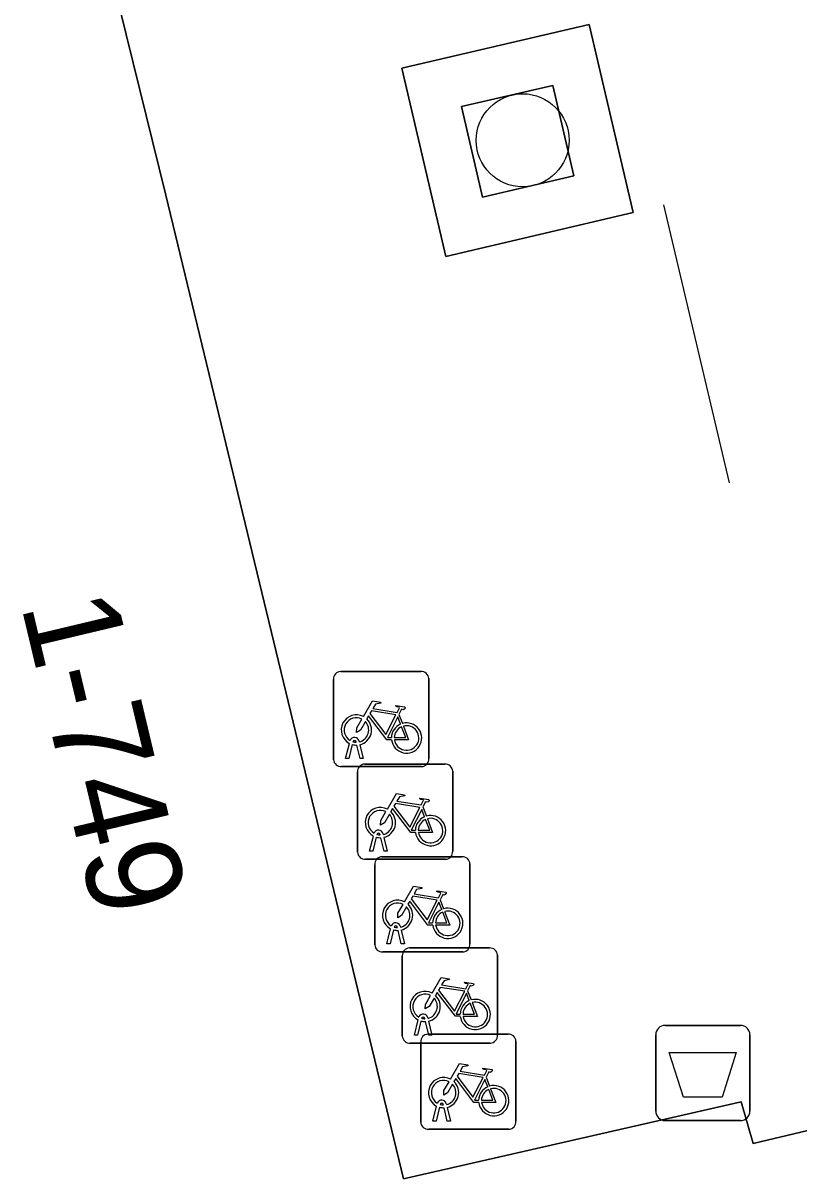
# Model space of a CAD drawing. Extents: x 160675 to 161153, y 383241 to 383714.
# Drawn here: x 160917.27 to 160925.43, y 383491.7 to 383503.84 of the extents above; entities that cross this region are included whole.
import ezdxf

# ---------------------------------------------------------------- set-up
doc = ezdxf.new("R2010")
doc.units = 0
for name, color, linetype in [('IMGEO_Afvalbak', 7, 'Continuous'), ('IMGEO_Boom', 7, 'Continuous'), ('IMGEO_Fietsenrek', 7, 'Continuous'), ('IMGEO_Groenvoorziening', 7, 'Continuous'), ('IMGEO_Lijnafwatering', 7, 'Continuous'), ('IMGEO_Muur', 7, 'Continuous'), ('IMGEO_Pand', 7, 'Continuous'), ('IMGEO_Pand_nummerreeks', 7, 'Continuous'), ('IMGEO_Voetpad_open', 7, 'Continuous')]:
    doc.layers.add(name, color=color, linetype=linetype)

msp = doc.modelspace()

# ---------------------------------------------------------------- linework, layer by layer
at = {"layer": 'IMGEO_Afvalbak'}
for p, q in [((160924.022, 383493.31), (160924.812, 383493.31)), ((160924.812, 383493.31), (160924.022, 383493.31)), ((160923.922, 383492.41), (160923.922, 383493.21)), ((160923.922, 383493.21), (160923.922, 383492.41)), ((160924.912, 383493.21), (160924.912, 383492.41)), ((160924.912, 383492.41), (160924.912, 383493.21)), ((160924.812, 383492.31), (160924.022, 383492.31)), ((160924.022, 383492.31), (160924.812, 383492.31))]:
    msp.add_line(p, q, dxfattribs=at)
msp.add_lwpolyline([(160924.065, 383493.024), (160924.769, 383493.024), (160924.62, 383492.554), (160924.214, 383492.554), (160924.065, 383493.024)], dxfattribs=at)
for centre, start, end in [((160924.022, 383493.21), 90, 180), ((160924.022, 383493.21), 90, 180), ((160924.812, 383493.21), 0, 90), ((160924.812, 383493.21), 360, 90), ((160924.022, 383492.41), 180, 270), ((160924.022, 383492.41), 180, 270), ((160924.812, 383492.41), 270, 0), ((160924.812, 383492.41), 270, 0)]:
    msp.add_arc(centre, 0.1, start, end, dxfattribs=at)
at = {"layer": 'IMGEO_Boom'}
msp.add_circle((160922.524, 383502.608), 0.489, dxfattribs=at)
at = {"layer": 'IMGEO_Fietsenrek'}
for p, q in [((160920.537, 383496.103), (160920.537, 383496.944)), ((160920.537, 383496.944), (160920.537, 383496.103)), ((160920.612, 383497.028), (160921.453, 383497.028)), ((160921.453, 383497.028), (160920.612, 383497.028)), ((160921.537, 383496.953), (160921.537, 383496.112)), ((160921.537, 383496.112), (160921.537, 383496.953)), ((160921.224, 383496.577), (160921.26, 383496.482)), ((160920.664, 383496.112), (160920.703, 383496.272)), ((160920.733, 383496.26), (160920.698, 383496.112)), ((160920.775, 383496.284), (160920.774, 383496.288)), ((160920.816, 383496.112), (160920.782, 383496.254)), ((160920.806, 383496.295), (160920.807, 383496.288)), ((160920.814, 383496.258), (160920.849, 383496.112)), ((160920.698, 383496.112), (160920.664, 383496.112)), ((160920.849, 383496.112), (160920.816, 383496.112)), ((160921.462, 383496.028), (160920.621, 383496.028)), ((160920.621, 383496.028), (160921.462, 383496.028)), ((160920.789, 383495.13), (160920.789, 383495.971)), ((160920.789, 383495.971), (160920.789, 383495.13)), ((160920.864, 383496.055), (160921.705, 383496.055)), ((160921.705, 383496.055), (160920.864, 383496.055)), ((160921.789, 383495.98), (160921.789, 383495.139)), ((160921.789, 383495.139), (160921.789, 383495.98)), ((160921.476, 383495.604), (160921.512, 383495.509)), ((160920.916, 383495.139), (160920.955, 383495.299)), ((160920.985, 383495.287), (160920.95, 383495.139)), ((160921.027, 383495.311), (160921.026, 383495.315)), ((160921.068, 383495.139), (160921.034, 383495.281)), ((160921.058, 383495.322), (160921.059, 383495.315)), ((160921.066, 383495.285), (160921.101, 383495.139)), ((160920.95, 383495.139), (160920.916, 383495.139)), ((160921.101, 383495.139), (160921.068, 383495.139)), ((160921.714, 383495.055), (160920.873, 383495.055)), ((160920.873, 383495.055), (160921.714, 383495.055)), ((160920.97, 383494.156), (160920.97, 383494.997)), ((160920.97, 383494.997), (160920.97, 383494.156)), ((160921.045, 383495.081), (160921.886, 383495.081)), ((160921.886, 383495.081), (160921.045, 383495.081)), ((160921.97, 383495.006), (160921.97, 383494.165)), ((160921.97, 383494.165), (160921.97, 383495.006)), ((160921.657, 383494.63), (160921.693, 383494.535)), ((160921.097, 383494.165), (160921.136, 383494.325)), ((160921.166, 383494.313), (160921.131, 383494.165)), ((160921.208, 383494.337), (160921.207, 383494.341)), ((160921.249, 383494.165), (160921.215, 383494.307)), ((160921.239, 383494.348), (160921.24, 383494.341)), ((160921.247, 383494.311), (160921.282, 383494.165)), ((160921.131, 383494.165), (160921.097, 383494.165)), ((160921.282, 383494.165), (160921.249, 383494.165)), ((160921.895, 383494.081), (160921.054, 383494.081)), ((160921.054, 383494.081), (160921.895, 383494.081)), ((160921.259, 383493.198), (160921.259, 383494.039)), ((160921.259, 383494.039), (160921.259, 383493.198)), ((160921.334, 383494.123), (160922.175, 383494.123)), ((160922.175, 383494.123), (160921.334, 383494.123)), ((160922.259, 383494.048), (160922.259, 383493.207)), ((160922.259, 383493.207), (160922.259, 383494.048)), ((160921.946, 383493.672), (160921.982, 383493.577)), ((160921.386, 383493.207), (160921.425, 383493.367)), ((160921.455, 383493.355), (160921.42, 383493.207)), ((160921.497, 383493.379), (160921.496, 383493.383)), ((160921.538, 383493.207), (160921.504, 383493.349)), ((160921.528, 383493.39), (160921.529, 383493.383)), ((160921.536, 383493.353), (160921.571, 383493.207)), ((160921.42, 383493.207), (160921.386, 383493.207)), ((160921.528, 383493.218), (160922.369, 383493.218)), ((160922.369, 383493.218), (160921.528, 383493.218)), ((160921.571, 383493.207), (160921.538, 383493.207)), ((160922.184, 383493.123), (160921.343, 383493.123)), ((160921.343, 383493.123), (160922.184, 383493.123)), ((160921.453, 383492.293), (160921.453, 383493.134)), ((160921.453, 383493.134), (160921.453, 383492.293)), ((160922.453, 383493.143), (160922.453, 383492.302)), ((160922.453, 383492.302), (160922.453, 383493.143)), ((160922.14, 383492.767), (160922.176, 383492.672)), ((160921.58, 383492.302), (160921.619, 383492.462)), ((160921.649, 383492.45), (160921.614, 383492.302)), ((160921.691, 383492.474), (160921.69, 383492.478)), ((160921.732, 383492.302), (160921.698, 383492.444)), ((160921.722, 383492.485), (160921.723, 383492.478)), ((160921.73, 383492.448), (160921.765, 383492.302)), ((160922.378, 383492.218), (160921.537, 383492.218)), ((160921.537, 383492.218), (160922.378, 383492.218)), ((160921.614, 383492.302), (160921.58, 383492.302)), ((160921.765, 383492.302), (160921.732, 383492.302))]:
    msp.add_line(p, q, dxfattribs=at)
for points in [[(160920.85, 383496.554), (160920.945, 383496.718), (160921.031, 383496.704), (160921.033, 383496.695), (160920.977, 383496.684), (160920.95, 383496.639), (160921.206, 383496.598)], [(160921.193, 383496.573), (160920.936, 383496.614), (160920.919, 383496.585), (160921.086, 383496.365), (160921.193, 383496.573)], [(160921.206, 383496.598), (160921.231, 383496.647), (160921.225, 383496.651), (160921.202, 383496.655), (160921.19, 383496.662), (160921.189, 383496.665), (160921.191, 383496.67), (160921.286, 383496.655), (160921.288, 383496.645), (160921.278, 383496.632), (160921.266, 383496.626), (160921.252, 383496.632), (160921.224, 383496.577)], [(160920.871, 383496.502), (160920.819, 383496.412), (160920.779, 383496.387), (160920.78, 383496.434), (160920.835, 383496.528)], [(160921.146, 383496.31), (160921.096, 383496.31), (160920.905, 383496.561), (160920.886, 383496.529)], [(160921.241, 383496.475), (160921.211, 383496.552), (160921.102, 383496.334), (160921.145, 383496.334)], [(160921.271, 383496.454), (160921.326, 383496.309), (160921.176, 383496.309)], [(160921.175, 383496.334), (160921.295, 383496.333), (160921.251, 383496.447)], [(160921.102, 383495.581), (160921.197, 383495.745), (160921.283, 383495.731), (160921.285, 383495.722), (160921.229, 383495.711), (160921.202, 383495.666), (160921.458, 383495.625)], [(160921.445, 383495.6), (160921.188, 383495.641), (160921.171, 383495.612), (160921.338, 383495.392), (160921.445, 383495.6)], [(160921.458, 383495.625), (160921.483, 383495.674), (160921.477, 383495.678), (160921.454, 383495.682), (160921.442, 383495.689), (160921.441, 383495.692), (160921.443, 383495.697), (160921.538, 383495.682), (160921.54, 383495.672), (160921.53, 383495.659), (160921.518, 383495.653), (160921.504, 383495.659), (160921.476, 383495.604)], [(160921.123, 383495.529), (160921.071, 383495.439), (160921.031, 383495.414), (160921.032, 383495.461), (160921.087, 383495.555)], [(160921.398, 383495.337), (160921.348, 383495.337), (160921.157, 383495.588), (160921.138, 383495.556)], [(160921.493, 383495.502), (160921.463, 383495.579), (160921.354, 383495.361), (160921.397, 383495.361)], [(160921.523, 383495.481), (160921.578, 383495.336), (160921.428, 383495.336)], [(160921.427, 383495.361), (160921.547, 383495.36), (160921.503, 383495.474)], [(160921.283, 383494.607), (160921.378, 383494.771), (160921.464, 383494.757), (160921.466, 383494.748), (160921.41, 383494.737), (160921.383, 383494.692), (160921.639, 383494.651)], [(160921.626, 383494.626), (160921.369, 383494.667), (160921.352, 383494.638), (160921.519, 383494.418), (160921.626, 383494.626)], [(160921.639, 383494.651), (160921.664, 383494.7), (160921.658, 383494.704), (160921.635, 383494.708), (160921.623, 383494.715), (160921.622, 383494.718), (160921.624, 383494.723), (160921.719, 383494.708), (160921.721, 383494.698), (160921.711, 383494.685), (160921.699, 383494.679), (160921.685, 383494.685), (160921.657, 383494.63)], [(160921.304, 383494.555), (160921.252, 383494.465), (160921.212, 383494.44), (160921.213, 383494.487), (160921.268, 383494.581)], [(160921.579, 383494.363), (160921.529, 383494.363), (160921.338, 383494.614), (160921.319, 383494.582)], [(160921.674, 383494.528), (160921.644, 383494.605), (160921.535, 383494.387), (160921.578, 383494.387)], [(160921.704, 383494.507), (160921.759, 383494.362), (160921.609, 383494.362)], [(160921.608, 383494.387), (160921.728, 383494.386), (160921.684, 383494.5)], [(160921.572, 383493.649), (160921.667, 383493.813), (160921.753, 383493.799), (160921.755, 383493.79), (160921.699, 383493.779), (160921.672, 383493.734), (160921.928, 383493.693)], [(160921.915, 383493.668), (160921.658, 383493.709), (160921.641, 383493.68), (160921.808, 383493.46), (160921.915, 383493.668)], [(160921.928, 383493.693), (160921.953, 383493.742), (160921.947, 383493.746), (160921.924, 383493.75), (160921.912, 383493.757), (160921.911, 383493.76), (160921.913, 383493.765), (160922.008, 383493.75), (160922.01, 383493.74), (160922, 383493.727), (160921.988, 383493.721), (160921.974, 383493.727), (160921.946, 383493.672)], [(160921.593, 383493.597), (160921.541, 383493.507), (160921.501, 383493.482), (160921.502, 383493.529), (160921.557, 383493.623)], [(160921.868, 383493.405), (160921.818, 383493.405), (160921.627, 383493.656), (160921.608, 383493.624)], [(160921.963, 383493.57), (160921.933, 383493.647), (160921.824, 383493.429), (160921.867, 383493.429)], [(160921.897, 383493.429), (160922.017, 383493.428), (160921.973, 383493.542)], [(160921.993, 383493.549), (160922.048, 383493.404), (160921.898, 383493.404)], [(160921.766, 383492.744), (160921.861, 383492.908), (160921.947, 383492.894), (160921.949, 383492.885), (160921.893, 383492.874), (160921.866, 383492.829), (160922.122, 383492.788)], [(160922.122, 383492.788), (160922.147, 383492.837), (160922.141, 383492.841), (160922.118, 383492.845), (160922.106, 383492.852), (160922.105, 383492.855), (160922.107, 383492.86), (160922.202, 383492.845), (160922.204, 383492.835), (160922.194, 383492.822), (160922.182, 383492.816), (160922.168, 383492.822), (160922.14, 383492.767)], [(160921.787, 383492.692), (160921.735, 383492.602), (160921.695, 383492.577), (160921.696, 383492.624), (160921.751, 383492.718)], [(160922.062, 383492.5), (160922.012, 383492.5), (160921.821, 383492.751), (160921.802, 383492.719)], [(160922.109, 383492.763), (160921.852, 383492.804), (160921.835, 383492.775), (160922.002, 383492.555), (160922.109, 383492.763)], [(160922.157, 383492.665), (160922.127, 383492.742), (160922.018, 383492.524), (160922.061, 383492.524)], [(160922.091, 383492.524), (160922.211, 383492.523), (160922.167, 383492.637)], [(160922.187, 383492.644), (160922.242, 383492.499), (160922.092, 383492.499)]]:
    msp.add_lwpolyline(points, dxfattribs=at)
for centre, radius, start, end in [((160920.615, 383496.95), 0.0779, 92.4484, 184.2845), ((160920.615, 383496.95), 0.0779, 92.4484, 184.2845), ((160921.459, 383496.95), 0.0779, 2.4484, 94.2845), ((160921.459, 383496.95), 0.0779, 2.4484, 94.2845), ((160920.777, 383496.413), 0.159, 62.6766, 242.1369), ((160920.777, 383496.413), 0.129, 63.3192, 238.903), ((160920.777, 383496.413), 0.129, 283.6043, 43.4302), ((160920.777, 383496.413), 0.159, 283.5766, 46.6042), ((160921.304, 383496.329), 0.159, 113.3408, 178.3217), ((160921.304, 383496.329), 0.159, 187.0065, 105.7708), ((160921.304, 383496.329), 0.129, 188.6715, 104.5883), ((160920.757, 383496.284), 0.0499, 12.8025, 158.6934), ((160921.304, 383496.329), 0.129, 113.923, 177.9556), ((160920.777, 383496.413), 0.159, 253.9967, 271.7867), ((160920.757, 383496.284), 0.0174, 12.8025, 163.4502), ((160920.777, 383496.413), 0.129, 253.415, 269.0204), ((160920.615, 383496.106), 0.0779, 182.4484, 274.2845), ((160920.615, 383496.106), 0.0779, 182.4484, 274.2845), ((160921.459, 383496.106), 0.0779, 272.4484, 4.2845), ((160921.459, 383496.106), 0.0779, 272.4484, 4.2845), ((160920.867, 383495.977), 0.0779, 92.4484, 184.2845), ((160920.867, 383495.977), 0.0779, 92.4484, 184.2845), ((160921.711, 383495.977), 0.0779, 2.4484, 94.2845), ((160921.711, 383495.977), 0.0779, 2.4484, 94.2845), ((160921.029, 383495.44), 0.159, 62.6766, 242.1369), ((160921.029, 383495.44), 0.129, 63.3192, 238.903), ((160921.029, 383495.44), 0.129, 283.6043, 43.4302), ((160921.029, 383495.44), 0.159, 283.5766, 46.6042), ((160921.556, 383495.356), 0.159, 113.3408, 178.3217), ((160921.556, 383495.356), 0.159, 187.0065, 105.7708), ((160921.556, 383495.356), 0.129, 188.6715, 104.5883), ((160921.009, 383495.311), 0.0499, 12.8025, 158.6934), ((160921.556, 383495.356), 0.129, 113.923, 177.9556), ((160921.029, 383495.44), 0.159, 253.9967, 271.7867), ((160921.009, 383495.311), 0.0174, 12.8025, 163.4502), ((160921.029, 383495.44), 0.129, 253.415, 269.0204), ((160920.867, 383495.133), 0.0779, 182.4484, 274.2845), ((160920.867, 383495.133), 0.0779, 182.4484, 274.2845), ((160921.711, 383495.133), 0.0779, 272.4484, 4.2845), ((160921.711, 383495.133), 0.0779, 272.4484, 4.2845), ((160921.048, 383495.003), 0.0779, 92.4484, 184.2845), ((160921.048, 383495.003), 0.0779, 92.4484, 184.2845), ((160921.892, 383495.003), 0.0779, 2.4484, 94.2845), ((160921.892, 383495.003), 0.0779, 2.4484, 94.2845), ((160921.21, 383494.466), 0.159, 62.6766, 242.1369), ((160921.21, 383494.466), 0.129, 63.3192, 238.903), ((160921.21, 383494.466), 0.129, 283.6043, 43.4302), ((160921.21, 383494.466), 0.159, 283.5766, 46.6042), ((160921.737, 383494.382), 0.159, 113.3408, 178.3217), ((160921.737, 383494.382), 0.159, 187.0065, 105.7708), ((160921.737, 383494.382), 0.129, 188.6715, 104.5883), ((160921.19, 383494.337), 0.0499, 12.8025, 158.6934), ((160921.737, 383494.382), 0.129, 113.923, 177.9556), ((160921.21, 383494.466), 0.159, 253.9967, 271.7867), ((160921.19, 383494.337), 0.0174, 12.8025, 163.4502), ((160921.21, 383494.466), 0.129, 253.415, 269.0204), ((160921.048, 383494.159), 0.0779, 182.4484, 274.2845), ((160921.048, 383494.159), 0.0779, 182.4484, 274.2845), ((160921.892, 383494.159), 0.0779, 272.4484, 4.2845), ((160921.892, 383494.159), 0.0779, 272.4484, 4.2845), ((160921.337, 383494.045), 0.0779, 92.4484, 184.2845), ((160921.337, 383494.045), 0.0779, 92.4484, 184.2845), ((160922.181, 383494.045), 0.0779, 2.4484, 94.2845), ((160922.181, 383494.045), 0.0779, 2.4484, 94.2845), ((160921.499, 383493.508), 0.159, 62.6766, 242.1369), ((160921.499, 383493.508), 0.129, 63.3192, 238.903), ((160921.499, 383493.508), 0.129, 283.6043, 43.4302), ((160921.499, 383493.508), 0.159, 283.5766, 46.6042), ((160922.026, 383493.424), 0.159, 113.3408, 178.3217), ((160922.026, 383493.424), 0.159, 187.0065, 105.7708), ((160922.026, 383493.424), 0.129, 113.923, 177.9556), ((160922.026, 383493.424), 0.129, 188.6715, 104.5883), ((160921.479, 383493.379), 0.0499, 12.8025, 158.6934), ((160921.499, 383493.508), 0.159, 253.9967, 271.7867), ((160921.479, 383493.379), 0.0174, 12.8025, 163.4502), ((160921.499, 383493.508), 0.129, 253.415, 269.0204), ((160921.337, 383493.201), 0.0779, 182.4484, 274.2845), ((160921.337, 383493.201), 0.0779, 182.4484, 274.2845), ((160921.531, 383493.14), 0.0779, 92.4484, 184.2845), ((160921.531, 383493.14), 0.0779, 92.4484, 184.2845), ((160922.181, 383493.201), 0.0779, 272.4484, 4.2845), ((160922.181, 383493.201), 0.0779, 272.4484, 4.2845), ((160922.375, 383493.14), 0.0779, 2.4484, 94.2845), ((160922.375, 383493.14), 0.0779, 2.4484, 94.2845), ((160921.693, 383492.603), 0.159, 62.6766, 242.1369), ((160921.693, 383492.603), 0.129, 63.3192, 238.903), ((160921.693, 383492.603), 0.129, 283.6043, 43.4302), ((160921.693, 383492.603), 0.159, 283.5766, 46.6042), ((160922.22, 383492.519), 0.159, 113.3408, 178.3217), ((160922.22, 383492.519), 0.159, 187.0065, 105.7708), ((160922.22, 383492.519), 0.129, 113.923, 177.9556), ((160922.22, 383492.519), 0.129, 188.6715, 104.5883), ((160921.673, 383492.474), 0.0499, 12.8025, 158.6934), ((160921.693, 383492.603), 0.159, 253.9967, 271.7867), ((160921.673, 383492.474), 0.0174, 12.8025, 163.4502), ((160921.693, 383492.603), 0.129, 253.415, 269.0204), ((160921.531, 383492.296), 0.0779, 182.4484, 274.2845), ((160921.531, 383492.296), 0.0779, 182.4484, 274.2845), ((160922.375, 383492.296), 0.0779, 272.4484, 4.2845), ((160922.375, 383492.296), 0.0779, 272.4484, 4.2845)]:
    msp.add_arc(centre, radius, start, end, dxfattribs=at)
at = {"layer": 'IMGEO_Groenvoorziening'}
msp.add_lwpolyline([(160922.102, 383502.012), (160923.06, 383502.233), (160922.841, 383503.183), (160921.883, 383502.963)], close=True, dxfattribs=at)
at = {"layer": 'IMGEO_Lijnafwatering'}
msp.add_lwpolyline([(160924.005, 383501.931), (160924.693, 383499.009)], dxfattribs=at)
at = {"layer": 'IMGEO_Muur'}
for points in [[(160923.223, 383503.825), (160921.255, 383503.364), (160921.718, 383501.387), (160923.686, 383501.848)], [(160922.102, 383502.012), (160921.883, 383502.963), (160922.841, 383503.183), (160923.06, 383502.233)]]:
    msp.add_lwpolyline(points, close=True, dxfattribs=at)
at = {"layer": 'IMGEO_Pand'}
msp.add_lwpolyline([(160979.419, 383505.022), (160930.969, 383493.5), (160924.945, 383492.067), (160924.82, 383492.508), (160921.273, 383491.697), (160918.775, 383502.03), (160918.011, 383505.128)], dxfattribs=at)
at = {"layer": 'IMGEO_Voetpad_open'}
msp.add_lwpolyline([(160918.011, 383505.128), (160918.775, 383502.03), (160921.273, 383491.697), (160924.82, 383492.508), (160924.945, 383492.067), (160930.969, 383493.5), (160930.66, 383494.777), (160929.639, 383499.27), (160928.362, 383504.703)], dxfattribs=at)
msp.add_lwpolyline([(160923.223, 383503.825), (160923.686, 383501.848), (160921.718, 383501.387), (160921.255, 383503.364)], close=True, dxfattribs=at)

# ---------------------------------------------------------------- texts
at = {"layer": 'IMGEO_Pand_nummerreeks'}
msp.add_text('1-749', height=1, rotation=283.3898, dxfattribs=at).set_placement((160917.251, 383497.727))

doc.saveas('drawing.dxf')
